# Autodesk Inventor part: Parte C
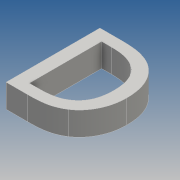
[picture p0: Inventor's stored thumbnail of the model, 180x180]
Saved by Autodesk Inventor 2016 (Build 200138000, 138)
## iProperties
Created: 2015-08
Part Number: Parte C
Material: Generic
Document SubType Name: Modeling
Designer: julian.chica
Density: 1 g/cm^3
Appearance: Default
Author: julian.chica
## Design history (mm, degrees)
sketch "Sketch1"
  geometry: L1 (-8.338, 20.108)-(8.338, 20.108); L2 (8.338, 20.108)-(8.338, 0); L3 (8.338, 0)-(-8.338, 0); L4 (-8.338, 0)-(-8.338, 20.108); 2 further points
  constraints: 1 coincident, 1 midpoint, 2 other
extrude "Extrusion1" new body sketch "Sketch1" distance "d1" = 5; taper "d2" = 0 deg
body "Solid1"
